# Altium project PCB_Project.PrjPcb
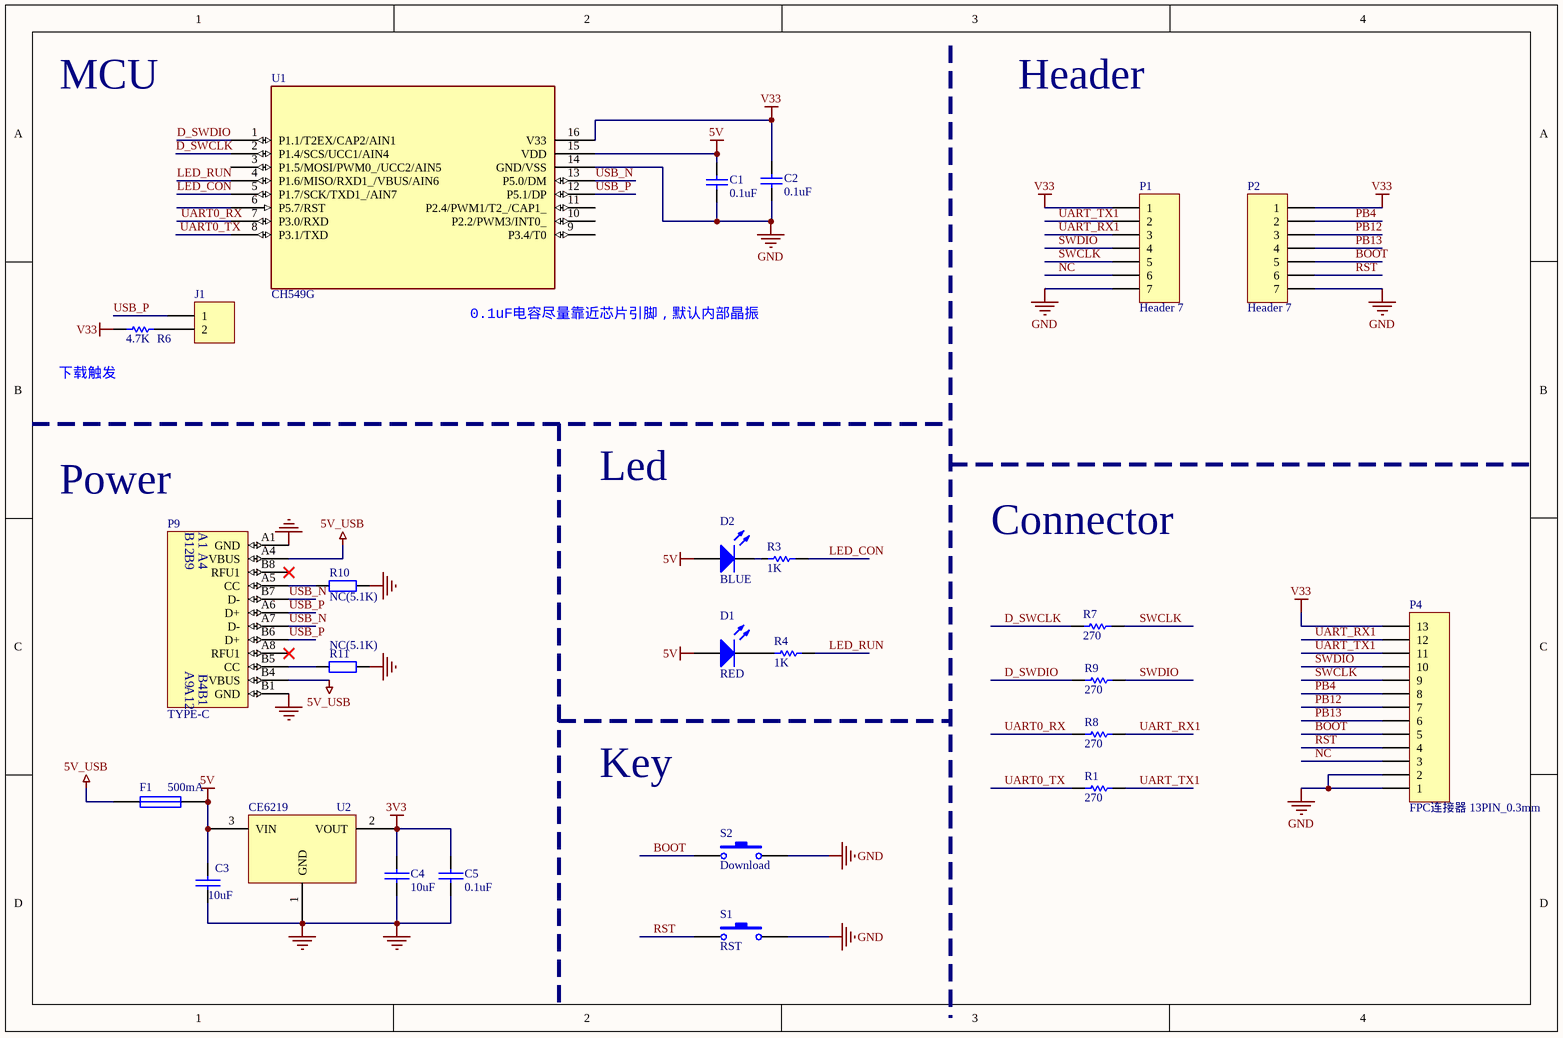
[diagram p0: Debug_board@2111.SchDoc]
1 sheet, 26 parts. Net scope: global (net labels, ports and power ports of the same name join across sheets).
Board file: Debug_board@2111.PcbDoc

## Sheet Debug_board@2111.SchDoc
size A4

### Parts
C1  0.1uF  [0603_C]
C2  0.1uF  [0603_C]
C3  10uF  [3216_C]
C4  10uF  [3216_C]
C5  0.1uF  [0603_C]
D1  RED  [0603+]
D2  BLUE  [0603+]
F1  500mA  [0603]
J1  Header 2  [SIP2-2.54MM]  (value not drawn)
P1  Header 7  [SIP7-2.54mm]
P2  Header 7  [SIP7-2.54mm]
P4  FPC连接器 13PIN_0.3mm  [FFC/FPC-13(6+7)-P0.3]
P9  TYPE-C  [TYPE-C-Receptacle-2.0]
R1  270  [0603]
R3  1K  [0603]
R4  1K  [0603]
R6  4.7K  [0603]
R7  270  [0603]
R8  270  [0603]
R9  270  [0603]
R10  NC(5.1K)  [0603]
R11  NC(5.1K)  [0603]
S1  RST  [贴片按键]
S2  Download  [贴片按键]
U1  CH549G  [SOP16]
U2  CE6219  [SOT-23]

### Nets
3V3: C4.1 C5.1 U2.2(VOUT)
5V: C1.1 C3.1 D1.1(A) D2.1(A) F1.2 U1.15(VDD) U2.3(VIN)
5V_USB: F1.1 P9.A4(VBUS) P9.B4(VBUS)
GND: C1.2 C2.2 C3.2 C4.2 C5.2 P1.7 P2.7 P4.1 P4.2 P9.A1(GND) P9.B1(GND) R10.2 R11.2 S1.2 S2.2 U1.14(GND/VSS) U2.1(GND)
V33: C2.1 P1.1 P2.1 P4.13 R6.2 U1.16(V33)
BOOT: P2.5 P4.5 S2.1
D_SWCLK: R7.2 U1.2(P1.4/SCS/UCC1/AIN4)
D_SWDIO: R9.2 U1.1(P1.1/T2EX/CAP2/AIN1)
LED_CON: R3.1 U1.5(P1.7/SCK/TXD1_/AIN7)
LED_RUN: R4.1 U1.4(P1.6/MISO/RXD1_/VBUS/AIN6)
NC: P1.6 P4.3
PB4: P2.2 P4.8
PB12: P2.3 P4.7
PB13: P2.4 P4.6
RST: P2.6 P4.4 S1.1
SWCLK: P1.5 P4.9 R7.1
SWDIO: P1.4 P4.10 R9.1
UART0_RX: R8.2 U1.7(P3.0/RXD)
UART0_TX: R1.2 U1.8(P3.1/TXD)
UART_RX1: P1.3 P4.12 R8.1
UART_TX1: P1.2 P4.11 R1.1
USB_N: P9.A7(D-) P9.B7(D-) U1.13(P5.0/DM)
USB_P: J1.1 P9.A6(D+) P9.B6(D+) U1.12(P5.1/DP)
NetD1_2: D1.2(K) R4.2
NetD2_2: D2.2(K) R3.2
NetJ1_2: J1.2 R6.1
NetP9_A5: P9.A5(CC) R10.1
NetP9_B5: P9.B5(CC) R11.1

Not connected (* = marked no-connect by the designer): P9 A8(RFU1)* B8(RFU1)*; U1 3(P1.5/MOSI/PWM0_/UCC2/AIN5) 6(P5.7/RST) 9(P3.4/T0) 10(P2.2/PWM3/INT0_) 11(P2.4/PWM1/T2_/CAP1_)

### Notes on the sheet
- MCU
- Header
- (near R6) 下载触发
- 0.1uF电容尽量靠近芯片引脚，默认内部晶振
- Power
- Led
- Connector
- Key

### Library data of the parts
C1 C2 = C0603: Capacitor
C3-C5 = CAP: Capacitor
D1 D2 = D0603: Typical RED, GREEN, YELLOW, AMBER GaAs LED
F1 = FUSE1: Fuse
J1 = Header 2: Header, 2-Pin
P1 P2 = Header 7: Header, 7-Pin
P4 = Header 13: Header, 13-Pin
P9 = TYPE-C1
R1 R3 R4 R6-R9 = R0603: Resistor
R10 R11 = Res2: Resistor
S1 S2 = SW-PB: Switch
U1 = CH549G: 8bit MCS51 MCU with ADC & USB type-C host & device & dual UART & SPI
U2 = LM1117_3.3V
